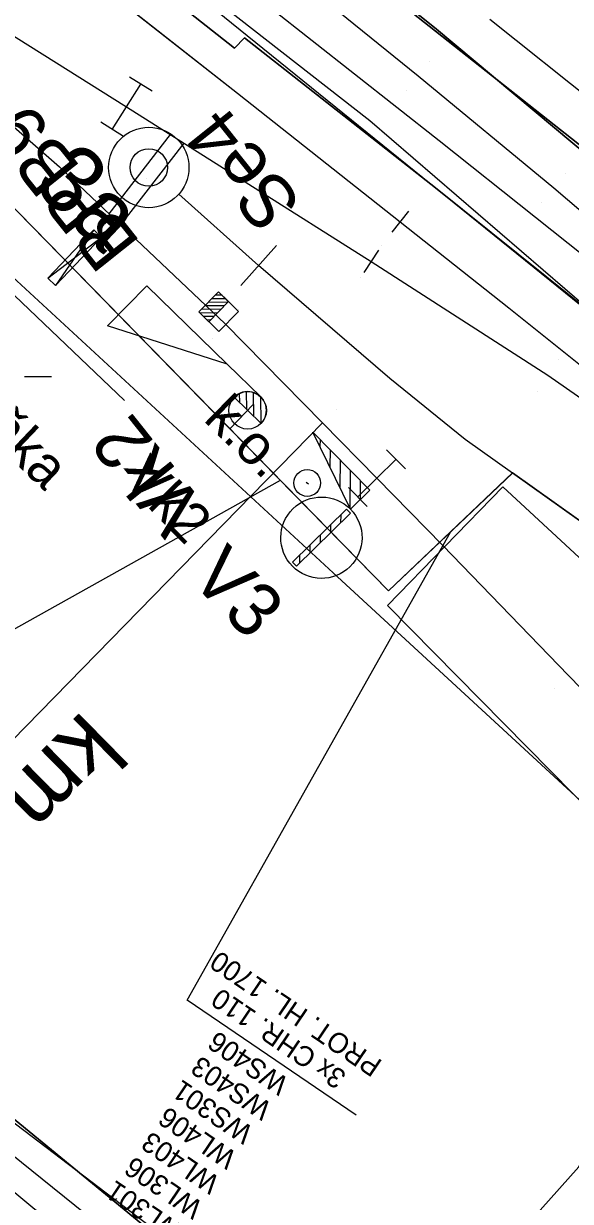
# Model space of a CAD drawing. Extents: x -621145 to -620023, y -1122866 to -1121971.
# Drawn here: x -620295.98 to -620275.55, y -1122728.09 to -1122684.12 of the extents above; entities that cross this region are included whole.
import ezdxf

# ---------------------------------------------------------------- set-up
doc = ezdxf.new("R2010")
doc.units = 0
for name, color, linetype in [('060601_EOV', 7, 'Continuous'), ('060604_ROZVODY_SEE', 7, 'Continuous'), ('CETIN', 7, 'Continuous'), ('GasNet', 7, 'Continuous'), ('POPIS KABELOVÉ TRASY', 7, 'Continuous'), ('PS 06-14-01_trasa_sdělovací_nové', 7, 'Continuous'), ('SEE', 7, 'Continuous'), ('SSZT', 7, 'Continuous'), ('Vrstva 1', 7, 'Continuous'), ('Vrstva 12', 7, 'Continuous'), ('Vrstva 16', 7, 'Continuous'), ('Vrstva 2', 7, 'Continuous'), ('Vrstva 23', 7, 'Continuous'), ('Vrstva 27', 7, 'Continuous'), ('Vrstva 3', 7, 'Continuous'), ('Vrstva 51', 7, 'Continuous'), ('Vrstva 53', 7, 'Continuous'), ('Vrstva 55', 7, 'Continuous'), ('Vrstva 56', 7, 'Continuous'), ('Vrstva 59', 7, 'Continuous'), ('Vrstva 62', 7, 'Continuous'), ('Vrstva 7', 7, 'Continuous'), ('ČD-T', 7, 'Continuous')]:
    doc.layers.add(name, color=color, linetype=linetype)

msp = doc.modelspace()

# ---------------------------------------------------------------- linework, layer by layer
at = {"layer": '060601_EOV'}
msp.add_lwpolyline([(-620235.16, -1122712.242), (-620240.174, -1122718.342), (-620243.025, -1122715.998), (-620248.321, -1122722.765), (-620259.889, -1122713.575), (-620277.713, -1122700.902), (-620282.346, -1122705.302), (-620297.82, -1122689.49), (-620304.222, -1122684.862), (-620310.815, -1122680.061), (-620322.228, -1122672.322), (-620343.182, -1122658.459), (-620368.499, -1122642.897), (-620411.557, -1122614.916), (-620424.156, -1122607.087), (-620443.525, -1122595.005), (-620456.111, -1122587.123), (-620447.823, -1122572.959), (-620450.948, -1122571.455), (-620470.592, -1122561.479), (-620499.61, -1122545.574), (-620522.038, -1122531.471), (-620538.89, -1122521.208), (-620599.215, -1122483.216)], dxfattribs=at)
at = {"layer": '060604_ROZVODY_SEE'}
msp.add_lwpolyline([(-620243.025, -1122715.998), (-620248.321, -1122722.765), (-620259.889, -1122713.575), (-620277.713, -1122700.902), (-620282.346, -1122705.302), (-620297.82, -1122689.49), (-620304.222, -1122684.862), (-620310.815, -1122680.061), (-620316.822, -1122675.988), (-620322.228, -1122672.322), (-620326.634, -1122669.408), (-620343.182, -1122658.459), (-620368.499, -1122642.897), (-620411.557, -1122614.916), (-620424.156, -1122607.087), (-620443.525, -1122595.005), (-620444.244, -1122596.151)], dxfattribs=at)
at = {"layer": 'CETIN'}
for points in [[(-620402.98, -1122642.16), (-620362.48, -1122674.84), (-620281.95, -1122736.09)], [(-620281.95, -1122736.09), (-620279.78, -1122731.91), (-620278.12, -1122730.04), (-620275.23, -1122726.8), (-620267.96, -1122716.51), (-620253.8, -1122706.08), (-620234.3, -1122721.82), (-620227.04, -1122727.67)]]:
    msp.add_lwpolyline(points, dxfattribs=at)
at = {"layer": 'GasNet'}
msp.add_lwpolyline([(-620349.5, -1122710.44), (-620336.68, -1122702.48), (-620334.91, -1122701.4), (-620329.86, -1122698.6), (-620318.09, -1122706.99), (-620309.56, -1122715.75), (-620284.55, -1122735.89), (-620286.51, -1122738.72), (-620281.311, -1122742.821), (-620280.83, -1122743.2), (-620261.03, -1122754.43), (-620247.22, -1122761.95), (-620220.34, -1122775.27), (-620203.57, -1122783.96)], dxfattribs=at)
at = {"layer": 'POPIS KABELOVÉ TRASY'}
for points in [[(-620286.396, -1122701.173), (-620300.7, -1122709.166), (-620307.023, -1122704.872)], [(-620283.547, -1122724.876), (-620289.869, -1122720.582), (-620280.029, -1122703.102)], [(-620289.869, -1122720.582), (-620289.869, -1122720.582)]]:
    msp.add_lwpolyline(points, dxfattribs=at)
at = {"layer": 'PS 06-14-01_trasa_sdělovací_nové'}
msp.add_lwpolyline([(-620248.321, -1122722.765), (-620259.889, -1122713.575), (-620277.711, -1122700.887), (-620282.346, -1122705.302), (-620297.82, -1122689.49), (-620310.815, -1122680.061), (-620322.228, -1122672.322), (-620343.182, -1122658.459), (-620368.499, -1122642.897), (-620411.557, -1122614.916), (-620456.111, -1122587.123), (-620544.953, -1122530.859), (-620538.89, -1122521.208), (-620538.89, -1122521.208), (-620538.89, -1122521.208)], dxfattribs=at)
at = {"layer": 'SEE'}
for points in [[(-620244.518, -1122694.296), (-620246.547, -1122692.66), (-620267.469, -1122718.6), (-620268.222, -1122719.534), (-620284.407, -1122704.62), (-620304.333, -1122686.26), (-620309.55, -1122681.453), (-620327.714, -1122669.483), (-620362.834, -1122646.339), (-620390.254, -1122629.02), (-620411.934, -1122614.961), (-620423.125, -1122608.012), (-620468.337, -1122579.91), (-620468.337, -1122579.91), (-620460.94, -1122568.103), (-620517.418, -1122533.032), (-620535.001, -1122522.477), (-620545.407, -1122539.454), (-620611.375, -1122497.696)], [(-620340.053, -1122630.257), (-620307.038, -1122645.433), (-620304.995, -1122662.882), (-620304.721, -1122665.223), (-620302.66, -1122666.96), (-620305.446, -1122670.265), (-620283.044, -1122687.742), (-620274.947, -1122694.711), (-620269.357, -1122688.084), (-620267.489, -1122689.555)]]:
    msp.add_lwpolyline(points, dxfattribs=at)
at = {"layer": 'SSZT'}
msp.add_lwpolyline([(-620879.238, -1122313.316), (-620842.993, -1122336.61), (-620835.049, -1122343.251), (-620812.66, -1122358.949), (-620764.902, -1122389.752), (-620688.594, -1122438.969), (-620596.981, -1122496.725), (-620576.744, -1122509.484), (-620506.746, -1122556.123), (-620447.293, -1122593.619), (-620363.271, -1122647.563), (-620313.966, -1122679.218), (-620306.51, -1122669.289), (-620273.137, -1122696.274), (-620258.422, -1122709.142), (-620248.072, -1122696.094)], dxfattribs=at)
at = {"layer": 'Vrstva 1'}
for p, q in [((-620287.398, -1122698.346), (-620288.271, -1122699.248)), ((-620282.346, -1122705.302), (-620288.271, -1122699.248)), ((-620277.713, -1122700.902), (-620278.485, -1122701.635)), ((-620259.889, -1122713.575), (-620277.713, -1122700.902)), ((-620282.346, -1122705.302), (-620278.485, -1122701.635))]:
    msp.add_line(p, q, dxfattribs=at)
for points in [[(-620348.688, -1122637.935), (-620341.5, -1122642.47), (-620339.854, -1122643.512), (-620333.156, -1122647.798), (-620327.653, -1122651.408), (-620321.139, -1122655.817), (-620314.146, -1122660.717), (-620307.245, -1122665.745), (-620300.366, -1122670.953), (-620293.063, -1122676.601), (-620287.47, -1122681.018), (-620281.24, -1122686.066), (-620276.174, -1122690.251), (-620272.417, -1122693.451), (-620267.757, -1122697.544), (-620266.519, -1122698.689), (-620262.242, -1122702.65), (-620256.103, -1122708.562), (-620249.907, -1122714.621), (-620245.657, -1122718.815), (-620238.557, -1122725.547), (-620230.199, -1122732.623), (-620229.854, -1122732.906)], [(-620347.616, -1122652.305), (-620342.456, -1122655.575), (-620322.526, -1122668.083), (-620312.925, -1122674.13), (-620301.163, -1122681.549), (-620292.126, -1122687.227), (-620282.992, -1122692.997), (-620276.394, -1122697.25), (-620266.758, -1122703.956), (-620255.894, -1122712.191)], [(-620322.526, -1122668.083), (-620313.097, -1122674.436), (-620308.214, -1122678.053), (-620306.7, -1122679.227), (-620305.337, -1122680.296), (-620302.152, -1122682.886), (-620294.636, -1122689.472), (-620288.443, -1122695.324), (-620284.812, -1122699.019), (-620282.778, -1122701.089), (-620280.313, -1122703.598), (-620275.628, -1122708.447), (-620262.902, -1122721.469), (-620255.487, -1122728.261), (-620248.439, -1122734.187)], [(-620288.271, -1122699.248), (-620297.82, -1122689.49), (-620304.222, -1122684.862), (-620310.815, -1122680.061), (-620311.612, -1122679.521), (-620316.822, -1122675.988)], [(-620300.906, -1122676.615), (-620294.546, -1122681.556), (-620287.988, -1122686.712), (-620281.909, -1122691.52), (-620277.852, -1122694.735), (-620274.362, -1122697.517), (-620269.944, -1122701.034), (-620263.761, -1122705.928), (-620255.894, -1122712.191), (-620251.107, -1122715.999), (-620247.589, -1122718.79), (-620245.37, -1122720.556), (-620245.065, -1122720.798), (-620243.16, -1122722.318), (-620236.673, -1122727.474), (-620229.854, -1122732.906), (-620228.705, -1122733.823), (-620228.351, -1122734.106), (-620222.324, -1122738.923)], [(-620300.906, -1122676.615), (-620294.546, -1122681.556), (-620293.844, -1122682.108), (-620287.988, -1122686.712), (-620281.909, -1122691.52), (-620277.852, -1122694.735), (-620274.362, -1122697.517), (-620269.944, -1122701.034), (-620263.761, -1122705.928), (-620255.894, -1122712.191), (-620251.107, -1122715.999), (-620247.589, -1122718.79), (-620245.37, -1122720.556), (-620245.065, -1122720.798), (-620243.16, -1122722.318), (-620236.673, -1122727.474), (-620229.854, -1122732.906)], [(-620277.713, -1122700.902), (-620279.474, -1122699.649), (-620282.292, -1122697.371), (-620287.195, -1122693.156)]]:
    msp.add_lwpolyline(points, dxfattribs=at)
at = {"layer": 'Vrstva 12'}
for points in [[(-620269.034, -1122691.627), (-620267.487, -1122692.828), (-620266.853, -1122693.319), (-620266.853, -1122693.319), (-620269.034, -1122691.627), (-620269.675, -1122692.369), (-620270.193, -1122692.979), (-620274.695, -1122689.218), (-620280.626, -1122684.271), (-620288.569, -1122677.912), (-620293.461, -1122674.083), (-620303.242, -1122666.538)], [(-620303.242, -1122666.538), (-620293.461, -1122674.083), (-620288.569, -1122677.912), (-620280.626, -1122684.271), (-620274.695, -1122689.218), (-620270.193, -1122692.979), (-620269.675, -1122692.369), (-620269.675, -1122692.369)]]:
    msp.add_lwpolyline(points, dxfattribs=at)
at = {"layer": 'Vrstva 16'}
msp.add_lwpolyline([(-620268.767, -1122698.19), (-620269.667, -1122699.332), (-620273.339, -1122696.067), (-620280.591, -1122690.258), (-620287.721, -1122684.651), (-620288.092, -1122685.04), (-620293.259, -1122680.96), (-620301.343, -1122674.65), (-620308.503, -1122669.28), (-620315.629, -1122664.052), (-620319.501, -1122661.293), (-620318.339, -1122659.55), (-620317.166, -1122660.468), (-620313.424, -1122663.148), (-620313.111, -1122662.768), (-620309.78, -1122665.216), (-620304.891, -1122668.836), (-620299.292, -1122673.151), (-620286.498, -1122683.168), (-620286.771, -1122683.508), (-620280.456, -1122688.482), (-620273.255, -1122694.212), (-620268.767, -1122698.19)], dxfattribs=at)
at = {"layer": 'Vrstva 2'}
for p, q in [((-620290.179, -1122690.492), (-620287.195, -1122693.156)), ((-620281.598, -1122691.128), (-620282.22, -1122691.912)), ((-620287.861, -1122693.902), (-620286.529, -1122692.41)), ((-620282.721, -1122692.577), (-620283.263, -1122693.417)), ((-620288.34, -1122694.521), (-620289.083, -1122694.53)), ((-620288.43, -1122694.39), (-620288.953, -1122694.397)), ((-620288.563, -1122694.261), (-620288.824, -1122694.264)), ((-620288.729, -1122694.919), (-620289.383, -1122694.928)), ((-620288.6, -1122694.786), (-620289.342, -1122694.796)), ((-620288.47, -1122694.653), (-620289.212, -1122694.663)), ((-620288.859, -1122695.052), (-620289.25, -1122695.057)), ((-620288.988, -1122695.185), (-620289.117, -1122695.187)), ((-620288.369, -1122696.837), (-620287.116, -1122698.058)), ((-620287.103, -1122699.048), (-620288.106, -1122698.071)), ((-620287.917, -1122697.934), (-620287.913, -1122698.259)), ((-620287.655, -1122697.863), (-620287.647, -1122698.518)), ((-620287.393, -1122697.895), (-620287.381, -1122698.777)), ((-620287.128, -1122698.047), (-620287.116, -1122699.036))]:
    msp.add_line(p, q, dxfattribs=at)
for points in [[(-620281.909, -1122691.52), (-620277.852, -1122694.735), (-620274.362, -1122697.517), (-620269.944, -1122701.034), (-620263.761, -1122705.928), (-620255.894, -1122712.191)], [(-620282.992, -1122692.997), (-620276.394, -1122697.25), (-620266.758, -1122703.956), (-620255.894, -1122712.191)]]:
    msp.add_lwpolyline(points, dxfattribs=at)
for points in [[(-620291.376, -1122693.905), (-620288.369, -1122696.837), (-620292.842, -1122695.409)], [(-620289.052, -1122695.25), (-620289.428, -1122694.884), (-620288.695, -1122694.132), (-620288.319, -1122694.498)], [(-620289.052, -1122695.25), (-620289.428, -1122694.884), (-620288.695, -1122694.132), (-620288.319, -1122694.498)], [(-620288.676, -1122695.617), (-620289.428, -1122694.884), (-620288.695, -1122694.132), (-620287.943, -1122694.865)]]:
    msp.add_lwpolyline(points, close=True, dxfattribs=at)
for centre, radius in [((-620291.298, -1122689.493), 1.5), ((-620291.298, -1122689.493), 0.7), ((-620287.605, -1122698.559), 0.7)]:
    msp.add_circle(centre, radius, dxfattribs=at)
msp.add_arc((-620287.605, -1122698.559), 0.7, 315.7256, 135.731, dxfattribs=at)
at = {"layer": 'Vrstva 23'}
msp.add_lwpolyline([(-620292.2, -1122698.187), (-620296.588, -1122694.01), (-620298.602, -1122695.675)], dxfattribs=at)
at = {"layer": 'Vrstva 27'}
msp.add_line((-620285.423, -1122701.244), (-620285.337, -1122701.296), dxfattribs=at)
msp.add_circle((-620285.38, -1122701.27), 0.5, dxfattribs=at)
at = {"layer": 'Vrstva 3'}
for p, q in [((-620291.169, -1122686.649), (-620292.015, -1122686.115)), ((-620292.66, -1122688.072), (-620291.592, -1122686.382)), ((-620292.237, -1122688.339), (-620293.083, -1122687.805)), ((-620284.812, -1122699.019), (-620302.722, -1122717.317)), ((-620284.897, -1122699.646), (-620284.906, -1122699.909)), ((-620284.518, -1122700.031), (-620284.538, -1122700.665)), ((-620282.415, -1122700.032), (-620281.714, -1122700.745)), ((-620284.147, -1122700.409), (-620284.163, -1122701.435)), ((-620282.065, -1122700.388), (-620283.491, -1122701.79)), ((-620283.775, -1122700.788), (-620283.788, -1122702.214)), ((-620283.396, -1122701.173), (-620283.402, -1122701.887)), ((-620283.842, -1122701.433), (-620283.141, -1122702.146)), ((-620284.127, -1122702.459), (-620284.135, -1122702.759)), ((-620284.512, -1122702.837), (-620284.515, -1122703.131)), ((-620284.897, -1122703.216), (-620284.9, -1122703.51)), ((-620285.282, -1122703.594), (-620285.278, -1122703.881)), ((-620285.662, -1122703.967), (-620285.663, -1122704.26))]:
    msp.add_line(p, q, dxfattribs=at)
for points in [[(-620285.169, -1122699.369), (-620283.042, -1122701.534), (-620283.768, -1122702.246)], [(-620285.932, -1122704.232), (-620285.786, -1122704.38), (-620283.763, -1122702.394), (-620283.909, -1122702.245)]]:
    msp.add_lwpolyline(points, close=True, dxfattribs=at)
msp.add_ellipse((-620284.849, -1122703.312), major_axis=(1.083, 1.064), ratio=0.999996, dxfattribs=at)
at = {"layer": 'Vrstva 51'}
msp.add_lwpolyline([(-620319.501, -1122661.293), (-620315.629, -1122664.052), (-620308.503, -1122669.28), (-620301.343, -1122674.65), (-620293.259, -1122680.96), (-620288.092, -1122685.04), (-620287.721, -1122684.651), (-620280.591, -1122690.258), (-620273.339, -1122696.067), (-620269.667, -1122699.332)], dxfattribs=at)
at = {"layer": 'Vrstva 53'}
for p, q in [((-620267.81, -1122694.49), (-620302.66, -1122666.96)), ((-620278.07, -1122701.42), (-620282.38, -1122705.84)), ((-620278.07, -1122701.42), (-620246.12, -1122731.05)), ((-620263.28, -1122725.23), (-620282.38, -1122705.84)), ((-620278.65, -1122739.48), (-620307.94, -1122715.53))]:
    msp.add_line(p, q, dxfattribs=at)
at = {"layer": 'Vrstva 55'}
for p, q in [((-620302.66, -1122666.96), (-620267.81, -1122694.49)), ((-620278.07, -1122701.42), (-620282.38, -1122705.84)), ((-620246.12, -1122731.05), (-620278.07, -1122701.42)), ((-620282.38, -1122705.84), (-620263.28, -1122725.23)), ((-620307.94, -1122715.53), (-620278.65, -1122739.48))]:
    msp.add_line(p, q, dxfattribs=at)
at = {"layer": 'Vrstva 56'}
msp.add_line((-620266.86, -1122693.31), (-620278.56, -1122683.97), dxfattribs=at)
at = {"layer": 'Vrstva 59'}
msp.add_line((-620295.937, -1122697.294), (-620294.937, -1122697.294), dxfattribs=at)
at = {"layer": 'Vrstva 62'}
for p, q in [((-620280.798, -1122685.52), (-620280.798, -1122685.52)), ((-620291.747, -1122686.622), (-620291.747, -1122686.622)), ((-620281.682, -1122686.611), (-620281.682, -1122686.611)), ((-620292.505, -1122687.832), (-620292.505, -1122687.832)), ((-620294.186, -1122688.929), (-620294.186, -1122688.929)), ((-620275.718, -1122689.718), (-620275.718, -1122689.718)), ((-620295.086, -1122690.014), (-620295.086, -1122690.014)), ((-620276.63, -1122690.785), (-620276.63, -1122690.785)), ((-620282.605, -1122692.402), (-620282.605, -1122692.402)), ((-620283.378, -1122693.592), (-620283.378, -1122693.592)), ((-620287.958, -1122694.78), (-620287.958, -1122694.78)), ((-620288.927, -1122695.869), (-620288.927, -1122695.869)), ((-620276.009, -1122696.653), (-620276.009, -1122696.653)), ((-620276.779, -1122697.848), (-620276.779, -1122697.848)), ((-620284.298, -1122698.515), (-620284.298, -1122698.515)), ((-620285.326, -1122699.523), (-620285.326, -1122699.523)), ((-620282.299, -1122700.556), (-620282.299, -1122700.556)), ((-620283.256, -1122701.623), (-620283.256, -1122701.623)), ((-620279.845, -1122703.061), (-620279.845, -1122703.061)), ((-620280.78, -1122704.135), (-620280.78, -1122704.135)), ((-620276.142, -1122708.929), (-620276.142, -1122708.929))]:
    msp.add_line(p, q, dxfattribs=at)
at = {"layer": 'Vrstva 7'}
for p, q in [((-620292.784, -1122691.222), (-620290.487, -1122688.263)), ((-620292.346, -1122691.636), (-620289.977, -1122688.585)), ((-620291.393, -1122689.919), (-620291.393, -1122689.919)), ((-620295.068, -1122693.629), (-620293.058, -1122692.089))]:
    msp.add_line(p, q, dxfattribs=at)
msp.add_lwpolyline([(-620293.349, -1122691.814), (-620294.777, -1122693.904), (-620295.068, -1122693.629), (-620293.349, -1122691.814), (-620293.058, -1122692.089), (-620294.777, -1122693.904)], dxfattribs=at)
at = {"layer": 'ČD-T'}
msp.add_lwpolyline([(-620358.852, -1122685.564), (-620308.585, -1122717.564), (-620291.218, -1122731.973), (-620279.983, -1122741.462), (-620260.482, -1122717.473), (-620252.938, -1122708.192), (-620233.103, -1122724.025), (-620218.511, -1122737.45), (-620206.638, -1122747.527), (-620193.132, -1122761.758), (-620178.165, -1122775.66), (-620170.996, -1122783.386), (-620164.655, -1122792.049), (-620156.507, -1122803.078), (-620151.811, -1122810.167)], dxfattribs=at)

# ---------------------------------------------------------------- texts
at = {"layer": 'POPIS KABELOVÉ TRASY'}
for s, p in [('PROT. HL. 1700', (-620282.533, -1122722.864)), ('3x CHR. 110', (-620283.868, -1122723.318)), ('WS406', (-620286.022, -1122723.547)), ('WS403', (-620286.654, -1122724.477)), ('WS301', (-620287.345, -1122725.368)), ('WL406', (-620287.965, -1122726.307)), ('WL403', (-620288.597, -1122727.238)), ('WL306', (-620289.229, -1122728.168)), ('WL301', (-620289.92, -1122729.059))]:
    msp.add_text(s, height=0.75, rotation=145.8181, dxfattribs=at).set_placement(p)
at = {"layer": 'Vrstva 1'}
msp.add_text('3a', height=2.5, rotation=316.6216, dxfattribs=at).set_placement((-620295.691, -1122690.195))
at = {"layer": 'Vrstva 23'}
msp.add_text('buňka', height=1.5, rotation=316.4112, dxfattribs=at).set_placement((-620299.139, -1122697.822))
at = {"layer": 'Vrstva 27'}
for s, height, rotation, p in [('k.o.', 1.5, 315.6422, (-620289.294, -1122698.925)), ('V3', 2, 314.0427, (-620289.814, -1122704.853))]:
    msp.add_text(s, height=height, rotation=rotation, dxfattribs=at).set_placement(p)
at = {"layer": 'Vrstva 3'}
for s, height, rotation, p in [('BPB9', 2, 128.542, (-620291.576, -1122692.306)), ('Se4', 2, 128.542, (-620285.524, -1122690.835)), ('Vk2', 2, 128.542, (-620289.121, -1122702.185)), ('Vk2', 1.5, 314.4932, (-620292.324, -1122701.175)), ('km 63,419', 2.5, 224.4932, (-620293.75, -1122709.718))]:
    msp.add_text(s, height=height, rotation=rotation, dxfattribs=at).set_placement(p)

doc.saveas('drawing.dxf')
